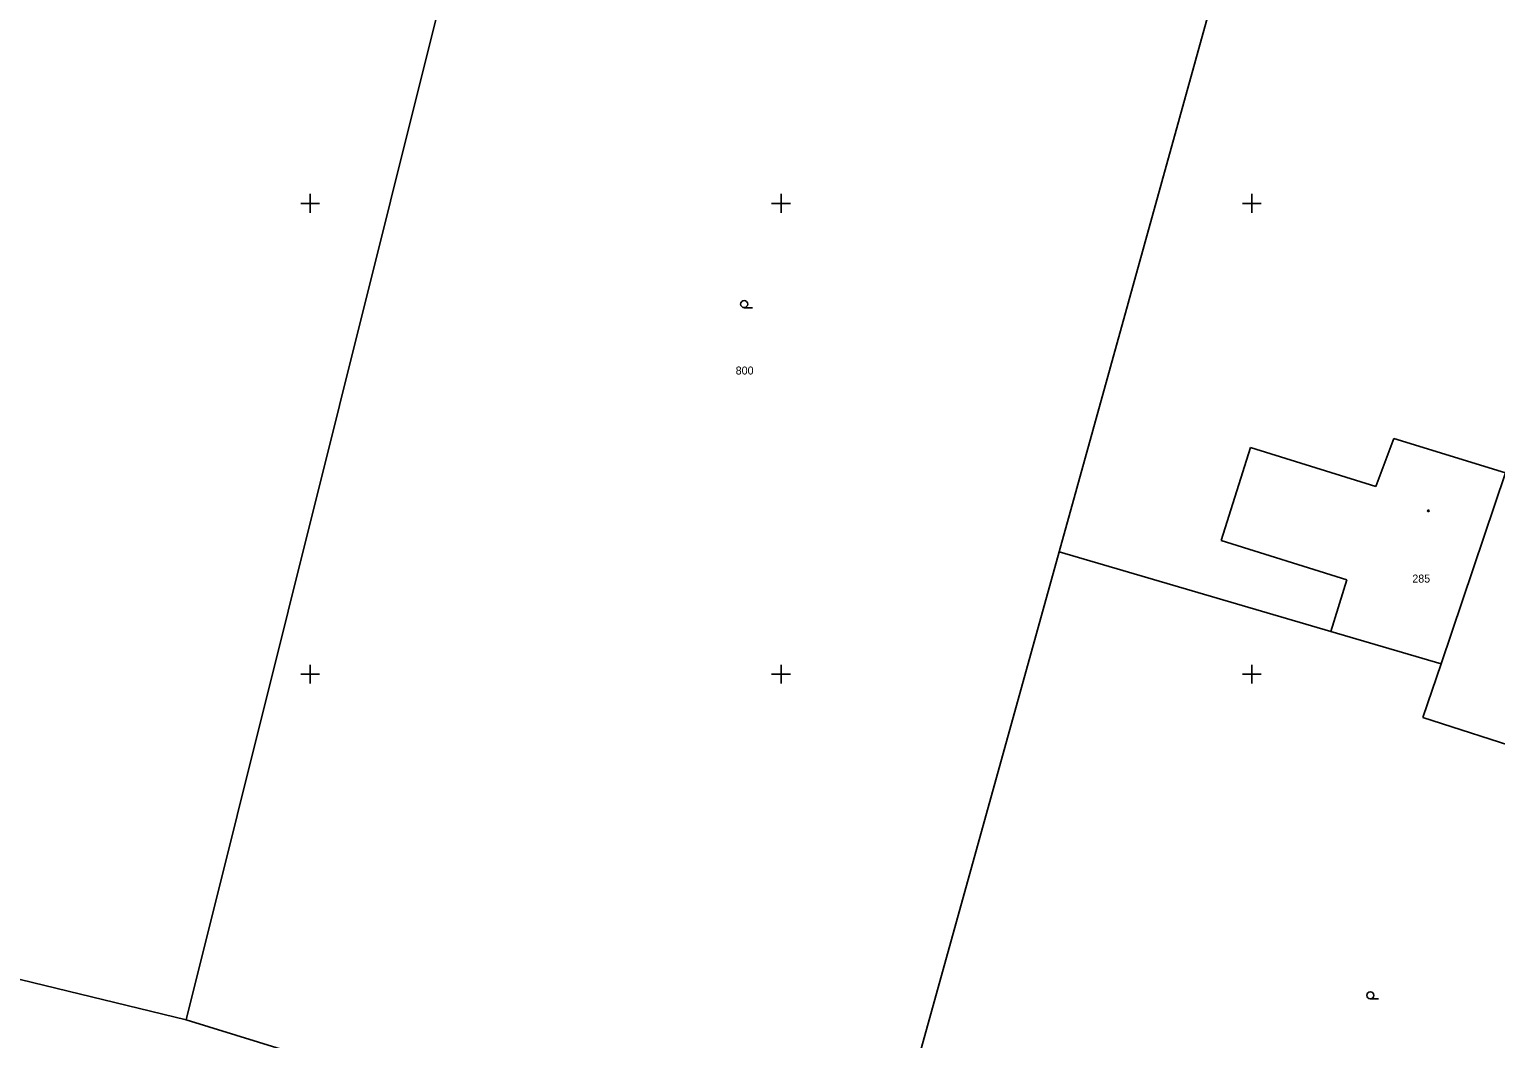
# Model space of a CAD drawing. Extents: x -703403 to -701924, y -1022520 to -1021856.
# Drawn here: x -702139.9 to -702062.1, y -1022369.4 to -1022315.8 of the extents above; entities that cross this region are included whole.
import ezdxf

# ---------------------------------------------------------------- set-up
doc = ezdxf.new("R2010")
doc.units = 0
for name, color, linetype in [('Z_hektometricka_sit', 7, 'Continuous'), ('Z_katastr_cisla_pozemkova', 7, 'Continuous'), ('Z_katastr_cisla_stavebni', 7, 'Continuous'), ('Z_katastr_hranice', 7, 'Continuous'), ('Z_katastr_vnitrni_kresba', 7, 'Continuous'), ('Z_katastr_znacky_budov', 7, 'Continuous'), ('Z_katastr_znacky_kultur', 7, 'Continuous')]:
    doc.layers.add(name, color=color, linetype=linetype)

msp = doc.modelspace()

# ---------------------------------------------------------------- linework, layer by layer
at = {"layer": 'Z_hektometricka_sit'}
for p, q in [((-702125, -1022324.5), (-702125, -1022325.5)), ((-702100, -1022324.5), (-702100, -1022325.5)), ((-702075, -1022324.5), (-702075, -1022325.5)), ((-702125.5, -1022325), (-702124.5, -1022325)), ((-702100.5, -1022325), (-702099.5, -1022325)), ((-702075.5, -1022325), (-702074.5, -1022325)), ((-702125, -1022349.5), (-702125, -1022350.5)), ((-702100, -1022349.5), (-702100, -1022350.5)), ((-702075, -1022349.5), (-702075, -1022350.5)), ((-702125.5, -1022350), (-702124.5, -1022350)), ((-702100.5, -1022350), (-702099.5, -1022350)), ((-702075.5, -1022350), (-702074.5, -1022350))]:
    msp.add_line(p, q, dxfattribs=at)
at = {"layer": 'Z_katastr_hranice'}
for p, q in [((-702131.59, -1022368.36), (-702110.86, -1022285.3)), ((-702076.91, -1022313.51), (-702085.23, -1022343.5)), ((-702064.95, -1022349.45), (-702061.52, -1022339.32)), ((-702095.24, -1022379.57), (-702085.23, -1022343.5)), ((-702085.23, -1022343.5), (-702070.81, -1022347.73)), ((-702070.81, -1022347.73), (-702064.95, -1022349.45)), ((-702065.92, -1022352.31), (-702064.95, -1022349.45)), ((-702032.46, -1022363.1), (-702065.92, -1022352.31)), ((-702161.37, -1022361.14), (-702131.59, -1022368.36)), ((-702131.59, -1022368.36), (-702095.24, -1022379.57))]:
    msp.add_line(p, q, dxfattribs=at)
at = {"layer": 'Z_katastr_vnitrni_kresba'}
for p, q in [((-702075.07, -1022337.96), (-702076.62, -1022342.91)), ((-702068.41, -1022340.04), (-702075.07, -1022337.96)), ((-702067.45, -1022337.48), (-702068.41, -1022340.04)), ((-702067.45, -1022337.48), (-702061.52, -1022339.32)), ((-702076.62, -1022342.91), (-702069.96, -1022344.99)), ((-702069.96, -1022344.99), (-702070.81, -1022347.73))]:
    msp.add_line(p, q, dxfattribs=at)
at = {"layer": 'Z_katastr_znacky_budov'}
msp.add_circle((-702065.622, -1022341.33), 0.0437, dxfattribs=at)
at = {"layer": 'Z_katastr_znacky_kultur'}
for p, q in [((-702101.958, -1022330.54), (-702101.521, -1022330.54)), ((-702068.708, -1022367.25), (-702068.271, -1022367.25))]:
    msp.add_line(p, q, dxfattribs=at)
for centre in [(-702101.958, -1022330.352), (-702068.708, -1022367.062)]:
    msp.add_circle(centre, 0.187, dxfattribs=at)

# ---------------------------------------------------------------- texts
at = {"layer": 'Z_katastr_cisla_pozemkova'}
msp.add_text('800', height=0.425, dxfattribs=at).set_placement((-702102.408, -1022334.09))
at = {"layer": 'Z_katastr_cisla_stavebni'}
msp.add_text('285', height=0.425, dxfattribs=at).set_placement((-702066.478, -1022345.14))

doc.saveas('drawing.dxf')
